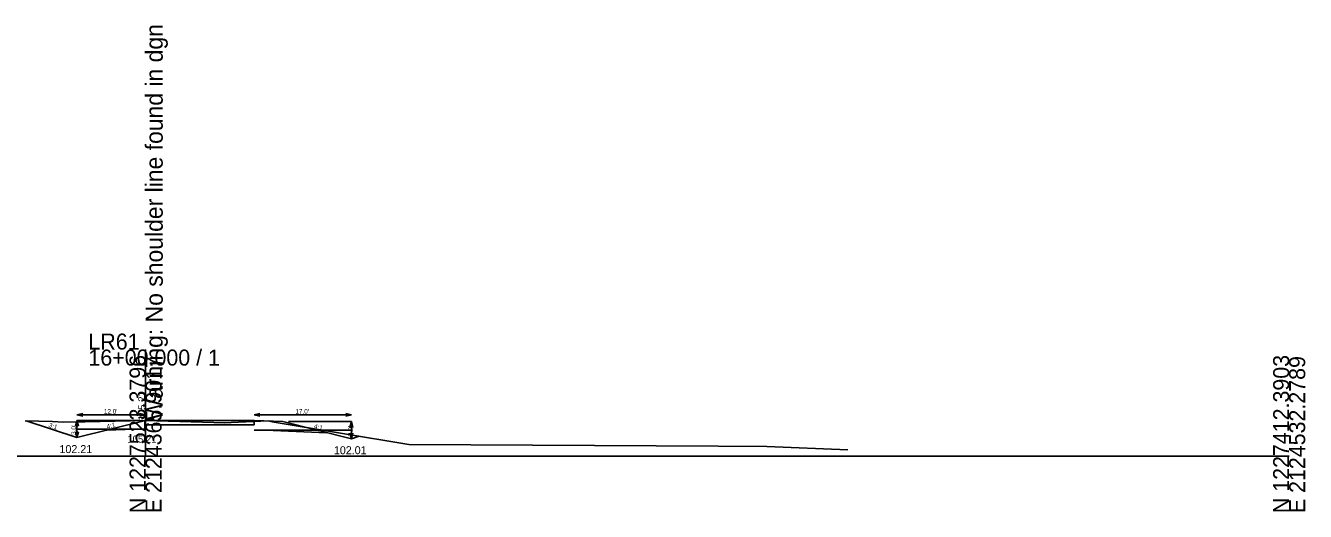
# Model space of a CAD drawing. Extents: x -26 to 1403, y -10 to 9574.
# Drawn here: x 1179 to 1402.8, y 5990.3 to 6075.3 of the extents above; entities that cross this region are included whole.
import ezdxf

# ---------------------------------------------------------------- set-up
doc = ezdxf.new("R2010")
doc.units = 0
for name, color, linetype in [('47', 7, 'Continuous'), ('XS_CELL', 7, 'Continuous'), ('XS_P_FINISHED_GRADE', 7, 'Continuous'), ('XS_P_FINISHED_GRADE_ELEV_TX', 7, 'Continuous'), ('XS_P_SUBGRADE_GRANULAR', 7, 'Continuous'), ('XS_P_SUBGRADE_PAVEMENT', 7, 'Continuous'), ('XS_P_TX_CLEARZONE', 7, 'Continuous'), ('XS_P_TX_DCH', 7, 'Continuous'), ('XS_P_TX_FS_BS', 7, 'Continuous'), ('XS_X_GROUND', 7, 'Continuous'), ('XS_X_GROUND_TX', 7, 'Continuous')]:
    doc.layers.add(name, color=color, linetype=linetype)

msp = doc.modelspace()

# ---------------------------------------------------------------- linework, layer by layer
at = {"layer": 'XS_CELL'}
for p, q in [((1200, 6000), (1200, 6018.62)), ((1000, 6000), (1200, 6000)), ((1200, 6000), (1400, 6000))]:
    msp.add_line(p, q, dxfattribs=at)
at = {"layer": 'XS_P_FINISHED_GRADE'}
for p, q in [((1188, 6003.21), (1179.11, 6006.17)), ((1200, 6006.21), (1188, 6003.21)), ((1200, 6006.21), (1219, 6006.21)), ((1219, 6006.21), (1224, 6006.01)), ((1224, 6006.01), (1236, 6003.01)), ((1236, 6003.01), (1237.34, 6003.46))]:
    msp.add_line(p, q, dxfattribs=at)
at = {"layer": 'XS_P_SUBGRADE_GRANULAR'}
for p, q in [((1187.8, 6004.71), (1200, 6004.71)), ((1198, 6004.71), (1193.24, 6004.52)), ((1200, 6004.71), (1198, 6004.71)), ((1236.2, 6004.51), (1219, 6004.51)), ((1219, 6004.51), (1221, 6004.51)), ((1221, 6004.51), (1231.71, 6004.08))]:
    msp.add_line(p, q, dxfattribs=at)
at = {"layer": 'XS_P_SUBGRADE_PAVEMENT'}
for p, q in [((1200, 6005.46), (1219, 6005.46)), ((1219, 6005.46), (1219, 6006.21))]:
    msp.add_line(p, q, dxfattribs=at)
at = {"layer": 'XS_P_TX_CLEARZONE'}
for p, q in [((1188, 6007.21), (1189, 6007.46)), ((1200, 6007.21), (1199, 6007.46)), ((1219, 6007.21), (1220, 6007.46)), ((1236, 6007.21), (1235, 6007.46)), ((1188, 6006.21), (1187.75, 6005.21)), ((1188, 6007.21), (1189, 6006.96)), ((1200, 6007.21), (1188, 6007.21)), ((1188, 6006.21), (1188.25, 6005.21)), ((1188, 6006.21), (1188, 6003.21)), ((1199, 6006.21), (1188, 6006.21)), ((1200, 6007.21), (1199, 6006.96)), ((1219, 6007.21), (1220, 6006.96)), ((1219, 6007.21), (1236, 6007.21)), ((1225, 6006.01), (1236, 6006.01)), ((1236, 6007.21), (1235, 6006.96)), ((1236, 6006.01), (1235.75, 6005.01)), ((1236, 6006.01), (1236, 6003.01)), ((1236, 6006.01), (1236.25, 6005.01)), ((1188, 6003.21), (1187.75, 6004.21)), ((1188, 6003.21), (1188.25, 6004.21)), ((1236, 6003.01), (1235.75, 6004.01)), ((1236, 6003.01), (1236.25, 6004.01))]:
    msp.add_line(p, q, dxfattribs=at)
at = {"layer": 'XS_X_GROUND'}
for p, q in [((1178.92, 6006.18), (1183.7, 6006.01)), ((1183.7, 6006.01), (1185.66, 6005.93)), ((1185.66, 6005.93), (1189.45, 6006)), ((1189.45, 6006), (1200, 6006.21)), ((1200, 6006.21), (1211.93, 6005.88)), ((1211.93, 6005.88), (1213.88, 6005.82)), ((1213.88, 6005.82), (1214.99, 6005.88)), ((1214.99, 6005.88), (1221.41, 6006.18)), ((1221.41, 6006.18), (1222.16, 6006)), ((1222.16, 6006), (1246.05, 6002)), ((1246.05, 6002), (1300.16, 6001.72)), ((1300.16, 6001.72), (1308.64, 6001.64)), ((1308.64, 6001.64), (1322.83, 6001.07))]:
    msp.add_line(p, q, dxfattribs=at)

# ---------------------------------------------------------------- texts
at = {"layer": '47'}
msp.add_text('Warning: No shoulder line found in dgn', height=3, rotation=90, dxfattribs=at).set_placement((1203, 6006.21))
at = {"layer": 'XS_CELL'}
for s, p in [('LR61', (1190, 6018.62)), ('16+00.000 / 1', (1190, 6015.82))]:
    msp.add_text(s, height=2.8, dxfattribs=at).set_placement(p)
for s, p in [('N 1227523.3796', (1200, 5990)), ('E 2124365.9017', (1202.8, 5990)), ('N 1227412.3903', (1400, 5990)), ('E 2124532.2789', (1402.8, 5990))]:
    msp.add_text(s, height=2.8, rotation=90, dxfattribs=at).set_placement(p)
at = {"layer": 'XS_P_FINISHED_GRADE_ELEV_TX'}
msp.add_text('105.21', height=1.25, rotation=90, dxfattribs=at).set_placement((1199.98, 6006.23))
at = {"layer": 'XS_P_TX_CLEARZONE'}
for s, p in [("12.0'", (1192.72, 6007.41)), ("17.0'", (1226.21, 6007.41))]:
    msp.add_text(s, height=0.8, dxfattribs=at).set_placement(p)
for p in [(1187.8, 6003.69), (1236.2, 6003.49)]:
    msp.add_text("3.0'", height=0.8, rotation=90, dxfattribs=at).set_placement(p)
at = {"layer": 'XS_P_TX_DCH'}
for s, p in [('102.21', (1184.94, 6000.51)), ('102.01', (1232.93, 6000.31))]:
    msp.add_text(s, height=1.4, dxfattribs=at).set_placement(p)
at = {"layer": 'XS_P_TX_FS_BS'}
for s, rotation, p in [('3:1', 341.5651, (1182.97, 6005.1)), ('4:1', 14.0362, (1193.29, 6004.74)), ('4:1', 345.9638, (1229.39, 6004.87))]:
    msp.add_text(s, height=0.8, rotation=rotation, dxfattribs=at).set_placement(p)
at = {"layer": 'XS_X_GROUND_TX'}
msp.add_text('105.21', height=1.25, rotation=360, dxfattribs=at).set_placement((1196.8, 6002.33))

doc.saveas('drawing.dxf')
